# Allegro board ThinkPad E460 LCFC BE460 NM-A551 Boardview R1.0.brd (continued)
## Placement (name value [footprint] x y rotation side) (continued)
RC55  49.9_0402_1%  [R_0402]  119.18 129.19 270 top
RC56  49.9_0402_1%  [R_0402]  102.57 100.9 270 top
RC67  10K_0402_5%  [R_0402]  111.73 146.58 0 top
RC70  10K_0402_5%  [R_0402]  109.84 145.9 270 top
RC71  10K_0402_5%  [R_0402]  113.15 145.39 270 top
RC74  10K_0402_5%  [R_0402]  110.46 142.72 90 top
RC83  1K_0402_5%  [R_0402]  105.14 143.62 270 top
RC84  20K_0402_5%  [R_0402]  106.03 143.62 270 top
RC88  10K_0402_5%  [R_0402]  90.66 138.08 0 top
RC92  499_0402_1%  [R_0402]  107.74 144.5 90 top
RC93  499_0402_1%  [R_0402]  108.63 144.5 90 top
RC95  8.2K_0402_5%  [R_0402]  123.55 150.83 90 top
RC97  1K_0402_5%  [R_0402]  123.63 154.46 180 top
RC98  20K_0402_5%  [R_0402]  121.09 154.46 180 top
RC99  1K_0402_5%  [R_0402]  123.63 153.58 180 top
RC100  20K_0402_5%  [R_0402]  121.09 153.58 180 top
RC101  1K_0402_5%  [R_0402]  123.63 152.69 180 top
RC102  33_0402_5%  [R_0402]  142.6 117.71 270 top
RC103  33_0402_5%  [R_0402]  135.11 117.71 270 top
RC104  1K_0402_5%  [R_0402]  86.14 93.5 0 bottom
RC105  1K_0402_5%  [R_0402]  86.85 94.83 90 bottom
RC106  4.7K_0402_5%  [R_0402]  111.56 149.13 180 top
RC107  4.7K_0402_5%  [R_0402]  108.74 149.64 0 top
RC108  10K_0402_5%  [R_0402]  88.77 137.41 270 bottom
RC109  0_0402_5%  [R0402_SHORT]  119.62 130.92 270 top
RC110  0_0402_5%  [R_0402]  141.59 137.9 270 top
RC117  1K_0402_5%  [R_0402]  143.11 136 270 top
RC118  1K_0402_5%  [R_0402]  141.59 136 270 top
RC120  100_0402_1%  [R_0402]  83.98 116.21 180 top
RC121  0_0402_5%  [R0402_SHORT]  83.98 117.1 180 top
RC123  10K_0402_5%  [R_0402]  88.04 99.73 0 top
RC124  0_0402_5%  [R0402_SHORT]  103.16 91.35 0 top
RC125  100_0402_1%  [R_0402]  101.38 91.35 0 top
RC126  0_0402_5%  [R0402_SHORT]  99.63 125.64 180 top
RC127  0_0402_5%  [R_0402]  91.42 141.76 270 top
RC132  0_0402_5%  [R0402_SHORT]  90.53 141.76 270 top
RC142  0_0402_5%  [R0402_SHORT]  83.98 117.99 180 top
RC143  100_0402_1%  [R_0402]  83.06 118.88 0 top
RC144  1K_0402_1%  [R_0402]  86.14 92.62 0 bottom
RC151  49.9_0402_1%  [R_0402]  116.11 129.18 270 top
RC152  49.9_0402_1%  [R_0402]  100.57 102.83 90 top
RC159  100K_0402_5%  [R_0402]  104.5 131.66 90 top
RC165  10K_0402_5%  [R_0402]  127.87 150.96 90 top
RC166  10K_0402_5%  [R_0402]  127.87 154.16 270 top
RC173  0_0603_5%  [R0603_SHORT]  134.36 146.5 180 top
RC176  0_0805_5%  [R0805_SHORT]  89.64 146.81 270 top
RC183  0_0402_5%  [R0402_SHORT]  103.16 89.82 0 top
RC184  100_0402_1%  [R_0402]  102.29 89.82 180 top
RC185  0_0402_5%  [R0402_SHORT]  99.63 126.52 180 top
RC189  100_0402_1%  [R_0402]  131.72 147.32 180 top
RC192  100_0402_1%  [R_0402]  130.8 148.28 0 top
RC200  49.9_0402_1%  [R_0402]  101.68 98.25 0 top
RC201  1K_0402_1%  [R_0402]  87.66 96.68 0 bottom
RC209  100K_0402_5%  [R_0402]  106.36 131.17 90 top
RC277  2.2K_0402_5%  [R_0402]  102.47 143.62 270 top
RC286  0_0402_5%  [R_0402]  131.73 154.46 0 top
RC287  2.2K_0402_5%  [R_0402]  103.36 143.62 270 top
RC292  10K_0402_5%  [R_0402]  175.29 108.59 0 top
RC294  1K_0402_5%  [R_0402]  88.03 98.8 0 top
RC295  0_0402_5%  [R0402_SHORT]  125.84 90.89 90 top
RC296  0_0402_5%  [R0402_SHORT]  116.62 151.8 0 bottom
RC297  1K_0402_5%  [R_0402]  134.09 114.79 270 top
RC298  8.2K_0402_5%  [R_0402]  130.84 140.49 0 top
RC299  1K_0402_5%  [R_0402]  137.27 115.42 270 top
RC300  20K_0402_5%  [R_0402]  123.55 149.97 270 top
RC301  20K_0402_5%  [R_0402]  134.98 114.79 270 top
RC302  20K_0402_5%  [R_0402]  136.38 115.42 270 top
RC304  0_0805_5%  [R_0805]  84.32 134.29 90 top
RC306  1K_0402_5%  [R_0402]  104.25 142.7 90 top
RC307  20K_0402_5%  [R_0402]  106.92 142.7 90 top
RC308  8.2K_0402_5%  [R_0402]  130.84 141.76 0 top
RC310  0_0402_5%  [R0402_SHORT]  143.11 137.9 270 top
RC311  0_0402_5%  [R0402_SHORT]  133.33 116.8 90 top
RC312  0_0402_5%  [R0402_SHORT]  134.8 128.43 180 top
RC313  0_0402_5%  [R0402_SHORT]  134.22 116.8 90 top
RC314  0_0402_5%  [R0402_SHORT]  132.11 128.43 0 top
RC315  0_0402_5%  [R0402_SHORT]  164.32 153.58 270 top
RC316  0_0402_5%  [R0402_SHORT]  165.4 153.59 0 top
RC317  0_0402_5%  [R0402_SHORT]  151.2 148.51 180 top
RC326  0_0402_5%  [R0402_SHORT]  88.75 129.06 180 bottom
RC330  0_0402_5%  [R0402_SHORT]  136.54 143.73 180 top
RC333  0_0402_5%  [R0402_SHORT]  136.39 142.87 270 top
RC341  0_0805_5%  [R0805_SHORT]  85.83 146.55 270 top
RC344  24.9_0402_1%  [R_0402]  100.44 108.69 270 top
RC347  10K_0402_5%  [R_0402]  176.21 107.71 180 top
RC348  33_0402_5%  [R_0402]  74.91 118.73 270 top
RC350  10K_0402_5%  [R_0402]  176.21 106.82 180 top
RC351  10K_0402_5%  [R_0402]  131.76 152.56 180 top
RC352  0_0402_5%  [R0402_SHORT]  139.24 141.91 0 top
RC353  10K_0402_5%  [R_0402]  132.7 152.61 90 top
RC354  1.5K_0402_5%  [R_0402]  87.57 132.13 180 bottom
RC355  100_0402_1%  [R_0402]  90.46 98.08 0 bottom
RC356  100_0402_1%  [R_0402]  90.46 99.85 0 bottom
RC358  100K_0402_1%  [R_0402]  90.52 101.34 0 top
RC359  113_0402_1%  [R_0402]  109.14 135.35 180 top
RC360  100_0402_1%  [R_0402]  101.63 134.65 0 top
RC361  200_0402_1%  [R_0402]  115.51 135.38 270 top
RC362  2.7K_0402_1%  [R_0402]  85.53 112.43 180 top
RC363  200_0402_1%  [R_0402]  111.03 134.12 270 top
RC364  0_0402_5%  [R0402_SHORT]  132.2 116.25 90 top
RC365  0_0402_5%  [R0402_SHORT]  130.93 139.49 180 top
RC366  0_0402_5%  [R_0402]  113.99 149.02 180 top
RC367  1K_0402_5%  [R_0402]  131.06 91.56 270 top
RC368  10K_0402_5%  [R_0402]  96.89 152.27 270 bottom
RC369  100_0402_1%  [R_0402]  83.08 119.78 0 top
RC370  100_0402_1%  [R_0402]  82.06 120.67 0 top
RC371  10K_0402_5%  [R_0402]  125.47 153.34 0 top
RC372  51_0402_1%  [R_0402]  89.43 107.74 180 bottom
RC373  51_0402_1%  [R_0402]  85.62 109.77 180 top
RC374  51_0402_1%  [R_0402]  85.62 108.45 180 top
RC375  10K_0402_5%  [R_0402]  105.48 145.87 270 top
RC376  10K_0402_5%  [R_0402]  104.59 145.87 270 top
RC377  2.2K_0402_1%  [R_0402]  103.7 145.87 270 top
RC378  2.2K_0402_1%  [R_0402]  102.81 145.87 270 top
RC379  10K_0402_5%  [R_0402]  201.39 125.65 180 top
RC380  1K_0402_5%  [R_0402]  137.43 135.53 180 top
RC382  10K_0402_5%  [R_0402]  84.68 95.83 90 top
RC383  1K_0402_5%  [R_0402]  86.53 101.16 270 top
RC384  0_0402_5%  [R_0402]  125.65 164.66 270 bottom
RC385  1K_0402_5%  [R_0402]  115.23 133.62 180 top
RC386  1K_0402_5%  [R_0402]  112.41 142.72 90 top
RC387  60.4_0402_1%  [R_0402]  90.49 99.44 0 top
RC388  10K_0402_5%  [R_0402]  100.81 144.62 90 top
RC389  0_0402_5%  [R0402_SHORT]  111.8 144.6 90 top
RC403  10K_0402_5%  [R_0402]  139.39 117.75 180 top
RC404  51_0402_1%  [R_0402]  89.48 103.32 180 bottom
RC405  0_0402_5%  [R_0402]  107.79 143.63 270 top
RC406  0_0402_5%  [R_0402]  111.45 142.72 90 top
RC407  0_0402_5%  [R_0402]  109.57 142.72 90 top
RC408  10K_0402_5%  [R_0402]  125.39 162.12 180 bottom
RC409  10K_0402_5%  [R_0402]  101.64 146.91 0 top
RC410  10K_0402_5%  [R_0402]  100.81 146.35 90 top
RD1  1.8K_0402_1%  [R_0402]  159.8 88.93 0 top
RD2  2_0402_1%  [R_0402]  159.8 88.04 0 top
RD3  1.8K_0402_1%  [R_0402]  163.43 89.01 270 top
RD4  24.9_0402_1%  [R_0402]  157.97 89.01 270 top
RD9  1.8K_0402_1%  [R_0402]  171.3 130.21 0 top
RD10  2_0402_1%  [R_0402]  159.32 130.5 90 top
RD11  1.8K_0402_1%  [R_0402]  172.19 127.54 0 top
RD12  24.9_0402_1%  [R_0402]  157.54 130.5 90 top
RD15  1.8K_0402_1%  [R_0402]  147.68 88.09 90 top
RD16  1.8K_0402_1%  [R_0402]  150.35 89.01 270 top
RD17  2_0402_1%  [R_0402]  146.79 88.09 90 top
RD18  24.9_0402_1%  [R_0402]  145.02 89.01 270 top
RD19  10K_0402_5%  [R_0402]  151.2 149.4 180 top
RD21  470_0402_5%  [R_0402]  158.27 100.49 0 top
RD23  100K_0402_5%  [R_0402]  175.46 133.9 180 top
RD24  10K_0402_5%  [R_0402]  174.54 133.02 0 top
RE1  43_0402_5%  [R_0402]  182.61 134.6 270 top
RE2  10K_0402_5%  [R_0402]  178.04 112.12 270 top
RE3  100K_0402_1%  [R_0402]  196.49 118 0 top
RE4  100K_0402_5%  [R_0402]  174.28 123.73 0 top
RE5  4.7K_0402_5%  [R_0402]  196.5 126.88 0 top
RE6  4.7K_0402_5%  [R_0402]  196.5 127.9 0 top
RE7  18K_0402_1%  [R_0402]  197.42 117.13 180 top
RE8  10K_0402_5%  [R_0402]  175.25 115.08 180 top
RE9  10K_0402_5%  [R_0402]  196 114.52 0 top
RE15  100K_0402_5%  [R_0402]  174.28 122.71 0 top
RE31  10K_0402_5%  [R_0402]  195.43 133.69 90 top
RE32  10K_0402_5%  [R_0402]  194.55 133.69 90 top
RE33  10K_0402_5%  [R_0402]  189.47 133.69 90 top
RE34  0_0402_5%  [R0402_SHORT]  189.41 136.05 180 top
RE39  10K_0402_5%  [R_0402]  196.5 125.13 0 top
RE40  0_0402_5%  [R0402_SHORT]  174.31 117.85 0 top
RE41  10K_0402_5%  [R_0402]  174.31 116.96 0 top
RE47  10K_0402_5%  [R_0402]  182.21 140.41 0 top
RE48  10K_0402_5%  [R_0402]  178.12 146.32 270 top
RE49  5.1K_0402_1%  [R_0402]  200.3 127.17 90 top
RE50  0_0402_5%  [R_0402]  203.12 110.03 180 bottom
RE51  0_0402_5%  [R_0402]  203.12 111.81 180 bottom
RE52  0_0402_5%  [R_0402]  203.12 110.92 180 bottom
RG1  0_0402_5%  [R_0402]  170.8 110.98 270 top
RG2  0_0402_5%  [R_0402]  175.3 104.95 0 top
RG4  100K_0402_5%  [R_0402]  175.24 114.21 180 top
RL1  0_0603_5%  [R0603_SHORT]  247.31 98.71 0 top
RL4  4.7K_0402_5%  [R_0402]  251.31 89.57 90 bottom
RL5  10K_0402_5%  [R_0402]  252.71 98.41 270 top
RL6  10K_0402_5%  [R_0402]  250.68 98.41 270 top
RL7  1K_0402_5%  [R_0402]  254.49 97.49 90 top
RL8  3.01K_0402_1%  [R_0402]  257.33 88.42 0 top
RL9  10K_0402_5%  [R_0402]  252.91 87.92 180 bottom
RL10  75_0805_5%  [R_0805]  266.94 80.33 90 bottom
RL11  75_0805_5%  [R_0805]  268.71 80.33 90 bottom
RL12  75_0805_5%  [R_0805]  274.19 79.97 90 bottom
RL13  75_0805_5%  [R_0805]  276.22 79.97 90 bottom
RL15  510_0402_1%  [R_0402]  284.39 86.01 0 top
RL16  510_0402_1%  [R_0402]  284.39 84.87 0 top
RL18  0_0402_5%  [R0402_SHORT]  250.17 87.92 0 bottom
RL22  47K_0402_5%  [R_0402]  245.4 100.11 0 bottom
RL23  100K_0402_5%  [R_0402]  241.03 100.79 90 bottom
RL24  10K_0402_5%  [R_0402]  246.31 99.09 180 bottom
RL25  0_0402_5%  [R_0402]  239.63 101.71 270 bottom
RL26  0_0402_5%  [R_0402]  253.21 88.03 180 top
RM2  0_0402_5%  [R0402_SHORT]  265.03 151.11 90 top
RM5  0_0402_5%  [R0402_SHORT]  263.63 151.11 90 top
RM8  0_0402_5%  [R0402_SHORT]  261.73 151.11 90 top
RM11  0_0402_5%  [R0402_SHORT]  260.33 151.11 90 top
RM13  0_0402_5%  [R0402_SHORT]  267.66 145.31 0 top
RM14  0_0603_5%  [R_0603]  254.31 139.24 0 top
RM15  0_0402_5%  [R0402_SHORT]  267.65 143.97 0 top
RM16  0_0402_5%  [R_0402]  266.73 141.4 0 top
RM17  0_0402_5%  [R_0402]  266.73 142.91 0 top
RM18  1M_0402_5%  [R_0402]  255.33 140.49 180 top
RM19  4.99K_0402_1%  [R_0402]  254.42 142.41 0 top
RM20  10K_0402_1%  [R_0402]  269.93 146.23 180 top
RM21  4.7K_0402_5%  [R_0402]  254.24 147.81 270 top
RM22  4.7K_0402_5%  [R_0402]  254.42 144.19 0 top
RM23  4.7K_0402_5%  [R_0402]  262.74 154.01 270 top
RM24  4.7K_0402_5%  [R_0402]  255.12 146.9 90 top
RM25  4.7K_0402_5%  [R_0402]  255.34 143.3 180 top
RM26  4.7K_0402_5%  [R_0402]  262.74 150.2 90 top
RM27  4.7K_0402_5%  [R_0402]  269.02 148.01 270 top
RM28  4.7K_0402_5%  [R_0402]  269.91 147.1 90 top
RM29  0_0402_5%  [R_0402]  254.42 145.97 0 top
RM30  0_0402_5%  [R_0402]  254.42 145.08 0 top
RM31  10K_0402_1%  [R_0402]  266.74 147.37 0 top
RM32  4.7K_0402_5%  [R_0402]  258.31 151.13 270 top
RM33  4.7K_0402_5%  [R_0402]  259.2 150.21 90 top
RM34  4.99K_0402_1%  [R_0402]  254.42 141.52 0 top
RPC2  33_0804_8P4R_5%  [RP_0804_8P4R]  131.44 113.63 90 top
RPC6  10K_0804_8P4R_5%  [RP_0804_8P4R]  134.79 149.63 0 top
RPC8  10K_0804_8P4R_5%  [RP_0804_8P4R]  112.24 151.35 90 bottom
RPC10  10K_0804_8P4R_5%  [RP_0804_8P4R]  110.91 155.34 0 top
RPC15  10K_0804_8P4R_5%  [RP_0804_8P4R]  89.01 130.21 0 bottom
RPC18  10K_0804_8P4R_5%  [RP_0804_8P4R]  131.87 149.9 180 top
RPC22  10K_0804_8P4R_5%  [RP_0804_8P4R]  126.97 148.94 270 top
RPC23  33_0804_8P4R_5%  [RP_0804_8P4R]  137.92 132.43 90 top
RPC24  33_0804_8P4R_5%  [RP_0804_8P4R]  141.6 132.43 90 top
RPC26  10K_0804_8P4R_5%  [RP_0804_8P4R]  90.15 134.53 180 bottom
RPC200  10K_0804_8P4R_5%  [RP_0804_8P4R]  126.41 150.54 180 top
RPE1  10K_0804_8P4R_5%  [RP_0804_8P4R]  174.16 121.43 0 top
RPE2  10K_0804_8P4R_5%  [RP_0804_8P4R]  182.24 111.09 90 top
RPE3  10K_0804_8P4R_5%  [RP_0804_8P4R]  179.32 111.09 90 top
RPE4  100K_0804_8P4R_5%  [RP_0804_8P4R]  193.39 134.85 270 top
RPE5  2.2K_0804_8P4R_5%  [RP_0804_8P4R]  184.75 137.77 270 top
RRE20  4.99K_0402_1%  [R_0402]  249.37 82.66 270 top
RRE21  4.7K_0402_5%  [R_0402]  244.58 81.74 90 top
RRE22  4.7K_0402_5%  [R_0402]  245.52 81.55 0 top
RRE23  4.7K_0402_5%  [R_0402]  247.38 81.74 90 top
RRE24  4.7K_0402_5%  [R_0402]  244.71 93.07 270 top
RRE25  4.7K_0402_5%  [R_0402]  250.22 86.01 0 bottom
RRE26  4.7K_0402_5%  [R_0402]  242.81 82.66 270 top
RRE27  4.7K_0402_5%  [R_0402]  243.69 82.66 270 top
RRE28  4.7K_0402_5%  [R_0402]  246.44 82.44 180 top
RRE29  4.7K_0402_5%  [R_0402]  248.27 82.66 270 top
RRE30  4.7K_0402_5%  [R_0402]  245.73 92.16 90 top
RRE32  0_0402_5%  [R0402_SHORT]  249.28 91.14 90 bottom
RV1  0_0402_5%  [R_0402]  74.24 155.49 180 top
RV2  0_0402_5%  [R_0402]  75.1 153.46 0 top
RV3  0_0402_5%  [R_0402]  74.24 154.61 180 top
RV4  0_0402_5%  [R_0402]  74.24 153.72 180 top
RV5  40.2_0402_1%  [R_0402]  51.16 133.69 90 bottom
RV6  100_0402_5%  [R_0402]  49.13 134.6 270 bottom
RV7  40.2_0402_1%  [R_0402]  46.08 133.69 90 bottom
RV8  100_0402_5%  [R_0402]  47.1 134.6 270 bottom
RV9  49.9_0402_1%  [R_0402]  64.6 170.11 270 top
RV10  10_0402_5%  [R_0402]  64.25 168.33 270 top
RV11  5.1K_0402_5%  [R_0402]  63.36 167.41 90 top
RV12  51.1_0402_1%  [R_0402]  50.12 173.18 270 top
RV13  51.1_0402_1%  [R_0402]  43.14 172.35 90 top
RV14  120_0402_1%  [R_0402]  52.18 133.69 90 bottom
RV15  10K_0402_5%  [R_0402]  14.71 130.54 270 top
RV16  243_0402_1%  [R_0402]  22.56 144.23 90 bottom
RV17  243_0402_1%  [R_0402]  20.17 130.54 270 top
RV18  4.99K_0402_1%  [R_0402]  20.73 145.16 270 bottom
RV19  4.99K_0402_1%  [R_0402]  19.84 144.24 90 bottom
RV24  4.99K_0402_1%  [R_0402]  21.01 145.16 270 top
RV25  4.99K_0402_1%  [R_0402]  21.9 144.24 90 top
RV26  40.2_0402_1%  [R_0402]  22.91 130.55 270 top
RV27  40.2_0402_1%  [R_0402]  22.02 129.64 90 top
RV28  243_0402_1%  [R_0402]  23.32 150.85 270 top
RV29  243_0402_1%  [R_0402]  18.47 164.18 90 bottom
RV30  4.99K_0402_1%  [R_0402]  19.79 149.97 90 top
RV31  4.99K_0402_1%  [R_0402]  20.68 150.88 270 top
RV36  4.99K_0402_1%  [R_0402]  22.48 149.96 90 bottom
RV37  4.99K_0402_1%  [R_0402]  21.13 150.87 270 bottom
RV38  40.2_0402_1%  [R_0402]  20.88 164.18 90 bottom
RV39  40.2_0402_1%  [R_0402]  19.99 165.1 270 bottom
RV40  1K_0402_5%  [R_0402]  47.12 169.45 0 bottom
RV43  10K_0402_5%  [R_0402]  67.03 134.93 270 bottom
RV44  100K_0402_5%  [R_0402]  64.52 131.88 270 bottom
RV47  1.69K_0402_1%  [R_0402]  53.98 134.58 270 bottom
RV48  1K_0402_1%  [R_0402]  53.09 134.58 270 bottom
RV49  10K_0402_5%  [R_0402]  83.74 138.27 0 top
RV50  10K_0402_5%  [R_0402]  85.17 139.28 180 top
RV51  0_0402_5%  [R_0402]  86.75 142.02 270 top
RV52  10K_0402_5%  [R_0402]  88.53 141.1 90 top
RV53  10K_0402_5%  [R_0402]  87.64 142.02 270 top
RV54  4.7K_0402_5%  [R_0402]  64.24 167.62 270 bottom
RV55  4.7K_0402_5%  [R_0402]  63.35 167.55 270 bottom
RV61  10K_0402_5%  [R_0402]  46.26 176 270 top
RV62  1K_0402_1%  [R_0402]  46.84 173.34 270 top
RV63  10K_0402_5%  [R_0402]  49.13 168 270 bottom
RV64  10K_0402_5%  [R_0402]  46.46 168 270 bottom
RV65  10K_0402_5%  [R_0402]  45.57 168 270 bottom
RV66  10K_0402_5%  [R_0402]  44.69 168 270 bottom
RV67  10K_0402_5%  [R_0402]  47.35 167.09 90 bottom
RV68  1M_0402_5%  [R_0402]  69.54 144.39 0 bottom
RV70  4.7K_0402_5%  [R_0402]  60.68 167.57 270 bottom
RV71  4.7K_0402_5%  [R_0402]  61.57 167.57 270 bottom
RV72  4.7K_0402_5%  [R_0402]  61.3 169.76 90 top
RV73  4.7K_0402_5%  [R_0402]  61.31 168.35 270 top
RV74  10K_0402_5%  [R_0402]  48.24 168 270 bottom
RV75  10K_0402_5%  [R_0402]  51.91 159.29 0 top
RV76  5.11K_0402_1%  [R_0402]  45.37 176 270 top
RV77  1K_0402_1%  [R_0402]  45.96 173.34 270 top
RV78  0_0402_5%  [R_0402]  70.03 160.69 180 bottom
RV79  0_0402_5%  [R_0402]  70.03 159.8 180 bottom
RV80  4.7K_0402_5%  [R_0402]  75.56 147.54 180 bottom
RV81  16.2K_0402_1%  [R_0402]  65.13 167.62 270 bottom
RV82  10K_0402_5%  [R_0402]  59.75 143.8 180 top
RV83  10K_0402_5%  [R_0402]  69.59 146.88 180 bottom
RV84  10K_0402_5%  [R_0402]  62.46 167.57 270 bottom
RV86  47K_0402_5%  [R_0402]  60.31 129.01 270 bottom
RV87  2.2K_0402_5%  [R_0402]  58.53 128.1 90 bottom
RV88  100K_0402_5%  [R_0402]  59.42 128.1 90 bottom
RV89  33_0402_5%  [R_0402]  19.06 168.06 0 bottom
RV90  33_0402_5%  [R_0402]  19.97 172.5 180 bottom
RV91  10K_0402_5%  [R_0402]  19.04 168.93 0 bottom
RV92  10K_0402_5%  [R_0402]  19.06 171.62 0 bottom
RV93  10K_0402_5%  [R_0402]  19.97 169.84 180 bottom
RV94  10K_0402_5%  [R_0402]  19.97 170.73 180 bottom
RV95  10K_0402_5%  [R_0402]  27.41 173.69 90 bottom
RV96  33_0402_5%  [R_0402]  26.18 169.74 0 bottom
RV97  33_0402_5%  [R_0402]  26.18 170.63 0 bottom
RV98  8.45K_0402_1%  [R_0402]  70.21 150.73 270 bottom
RV99  2K_0402_1%  [R_0402]  69.32 150.73 270 bottom
RV100  10K_0402_1%  [R_0402]  70.87 154.67 270 bottom
RV101  4.75K_0402_1%  [R_0402]  69.98 153.75 90 bottom
RV102  10K_0402_1%  [R_0402]  70.21 152 90 bottom
RV103  4.75K_0402_1%  [R_0402]  69.32 152.91 270 bottom
RV104  3.24K_0402_1%  [R_0402]  70.21 148.09 90 bottom
RV105  5.62K_0402_1%  [R_0402]  69.32 149 270 bottom
RV106  4.7K_0402_5%  [R_0402]  75.56 146.65 180 bottom
RV107  0_0402_5%  [R_0402]  69.12 155.61 0 bottom
RV108  0_0402_5%  [R_0402]  68.63 156.63 0 bottom
RV109  0_0402_5%  [R_0402]  68.61 157.77 0 bottom
RV111  2.2K_0402_5%  [R_0402]  71.55 162.82 0 bottom
RV112  0_0402_5%  [R_0402]  48.24 167.62 270 top
RV113  0_0402_5%  [R_0402]  48.11 175.09 90 top
RV114  0_0402_5%  [R0402_SHORT]  47.15 176 270 top
RV115  4.7K_0402_5%  [R_0402]  75.5 148.94 180 bottom
RV116  0_0402_5%  [R0402_SHORT]  26.25 170.39 180 top
RV117  0_0402_5%  [R0402_SHORT]  26.25 171.3 180 top
RV118  10K_0402_5%  [R_0402]  75.09 155.61 0 bottom
RV119  10K_0402_5%  [R_0402]  75.36 156.63 0 bottom
RV120  10K_0402_5%  [R_0402]  75.09 157.77 0 bottom
RV121  10K_0402_5%  [R_0402]  73.01 155.63 270 bottom
RV122  10K_0402_5%  [R_0402]  74 154.69 90 bottom
RV123  10K_0402_5%  [R_0402]  73.07 156.63 0 bottom
RV124  10K_0402_5%  [R_0402]  71.04 156.63 0 bottom
RV125  10K_0402_5%  [R_0402]  73.06 157.77 0 bottom
RV126  10K_0402_5%  [R_0402]  71.03 157.77 0 bottom
RV129  10K_0402_5%  [R_0402]  39.66 125.81 90 bottom
RV130  0_0402_5%  [R0402_SHORT]  45.5 132.24 0 bottom
RV134  47K_0402_5%  [R_0402]  73.64 158.35 270 top
RV135  10K_0402_5%  [R_0402]  72.75 157.44 90 top
RV136  0_0402_5%  [R0402_SHORT]  76.99 152.18 0 bottom
RV137  100K_0402_5%  [R_0402]  77.91 153.07 180 bottom
RV138  470_0402_5%  [R_0402]  78.92 157.39 180 bottom
RV139  10K_0402_5%  [R_0402]  76.99 150.4 0 bottom
RV140  0_0402_5%  [R_0402]  75.5 150.65 180 bottom
RV141  300_0402_5%  [R_0402]  51.29 129.55 180 bottom
RV142  10K_0402_5%  [R_0402]  55.89 131.48 180 bottom
RV143  100K_0402_5%  [R_0402]  38.77 125.81 90 bottom
RV152  100K_0402_5%  [R_0402]  55.05 174.33 180 top
RV153  22K_0402_5%  [R_0402]  55.91 174.33 0 top
SW1  NTC010-AK1G-B160T_4P  [SW_NTC010-AK1G-B160T_4P]  261 161.82 20 top
T3  PAD  [TPC12]  91.8 104.81 180 bottom
T4  PAD  [TPC12]  90.53 105.7 180 bottom
T5  PAD  [TPC12]  90.66 102.9 180 bottom
T6  PAD  [TPC12]  90.53 104.17 180 bottom
T8  PAD  [TPC12]  101.89 104.88 0 top
T9  PAD  [TPC12]  88.64 108.68 180 bottom
T10  PAD  [TPC12]  85.18 111.4 0 top
T11  PAD  [TPC12]  89.96 108.73 180 bottom
T12  PAD  [TPC12]  85.62 107.56 0 top
T13  PAD  [TPC12]  90.32 106.98 180 bottom
T14  PAD  [TPC12]  91.8 106.08 180 bottom
T15  PAD  [TPC12]  91.25 108.71 180 bottom
T16  PAD  [TPC12]  84.75 102.66 0 top
T18  PAD  [TPC12]  131.51 133.62 270 top
T19  PAD  [TPC12]  90.42 110.16 180 bottom
T20  PAD  [TPC12]  91.51 107.44 180 bottom
T23  PAD  [TPC12]  253.6 97.95 180 top
T24  PAD  [TPC12]  251.7 97.95 180 top
T49  PAD  [TPC12]  115.07 130.69 0 top
T50  PAD  [TPC12]  117.34 132.38 0 top
T52  PAD  [TPC12]  102.22 111.54 0 top
T53  PAD  [TPC12]  100.69 111.54 0 top
T56  PAD  [TPC12]  116.32 131.62 0 top
T59  PAD  [TPC12]  91.17 95.16 180 bottom
T60  PAD  [TPC12]  94.43 102.28 180 bottom
T61  PAD  [TPC12]  115.44 132.74 0 top
T62  PAD  [TPC12]  128.24 144.06 0 top
TC118  PAD  [TPC12]  118.08 130.32 0 top
TC119  Test_Point_40MIL  [TPC40]  111.7 141.09 180 bottom
TC120  Test_Point_40MIL  [TPC40]  111.93 139.7 180 bottom
TG1  PAD  [TPC12]  176.07 105.89 0 top
TL1  BOTHHAND-NA69LF  [TAIMA_IH-189-A_24P]  263.93 93.67 0 bottom
TP22  PAD  [TPC12]  91.28 136.83 0 top
TP23  PAD  [TPC12]  88.11 136.8 0 top
TP24  PAD  [TPC12]  115.16 151.79 180 bottom
TP25  PAD  [TPC12]  90.26 139.11 180 bottom
TP26  PAD  [TPC12]  113.78 151.84 180 bottom
TP27  PAD  [TPC12]  91.64 139.29 180 bottom
TP29  PAD  [TPC12]  128.8 139.09 0 top
TP30  PAD  [TPC12]  88.89 139.37 180 bottom
TP31  PAD  [TPC12]  88.87 140.81 180 bottom
TP32  PAD  [TPC12]  89.96 97.43 0 top
TP33  PAD  [TPC12]  91.79 140.74 180 bottom
TP34  PAD  [TPC12]  117.32 155.24 180 bottom
TP35  PAD  [TPC12]  115.94 155.27 180 bottom
TP36  PAD  [TPC12]  90.14 96.69 180 bottom
TP37  PAD  [TPC12]  128.28 90.43 0 top
TP38  PAD  [TPC12]  89.78 95.3 180 bottom
TP39  PAD  [TPC12]  128.25 91.75 0 top
TP40  PAD  [TPC12]  91.54 96.77 180 bottom
TP41  PAD  [TPC12]  88.24 95.31 180 bottom
TP42  PAD  [TPC12]  87.11 91.26 180 bottom
TP43  PAD  [TPC12]  113.96 131.44 0 top
TP44  PAD  [TPC12]  88.99 92.43 0 top
TP45  PAD  [TPC12]  114.09 132.66 0 top
TP46  PAD  [TPC12]  90.29 92.45 0 top
TP47  PAD  [TPC12]  91.61 93.8 0 top
TP48  PAD  [TPC12]  88.9 92.63 180 bottom
TP49  PAD  [TPC12]  114.52 153.46 180 bottom
TP50  PAD  [TPC12]  88.86 89.92 180 bottom
TP51  PAD  [TPC12]  115.92 153.46 180 bottom
TP52  PAD  [TPC12]  90.41 92.7 180 bottom
TP53  PAD  [TPC12]  88.82 91.28 180 bottom
TP54  PAD  [TPC12]  117.34 156.64 180 bottom
TP55  PAD  [TPC12]  88.76 88.56 180 bottom
TP56  PAD  [TPC12]  90.3 89.86 180 bottom
TP57  PAD  [TPC12]  90.32 88.49 180 bottom
TP58  PAD  [TPC12]  90.3 91.23 180 bottom
TP59  PAD  [TPC12]  119.4 135.07 0 top
TP60  PAD  [TPC12]  117.06 134.92 0 top
TP61  PAD  [TPC12]  90.26 95.07 0 top
TP62  PAD  [TPC12]  90.29 93.77 0 top
TP63  PAD  [TPC12]  91.59 95.09 0 top
TP64  PAD  [TPC12]  90.04 137.71 180 bottom
TP65  PAD  [TPC12]  88.99 93.7 0 top
TP66  PAD  [TPC12]  91.79 137.46 180 bottom
TP67  PAD  [TPC12]  91.41 136.04 180 bottom
TP68  PAD  [TPC12]  90.01 136.29 180 bottom
TP69  Test_Point_40MIL  [TPC40]  267.41 140.01 0 top
TP70  Test_Point_40MIL  [TPC40]  252.6 141.02 90 top
TP71  Test_Point_40MIL  [TPC40]  244.96 91.22 180 bottom
TP72  Test_Point_40MIL  [TPC40]  209.1 91.17 0 top
TP73  Test_Point_40MIL  [TPC40]  224.97 91.35 90 top
TP74  PAD  [TPC12]  90.26 140.76 180 bottom
TP85  PAD  [TPC12]  100.93 110.13 0 top
TP86  PAD  [TPC12]  103.24 109.74 0 top
TP87  PAD  [TPC12]  114.14 122.47 0 top
TP88  PAD  [TPC12]  114.06 124.76 0 top
TP89  PAD  [TPC12]  91.18 93.84 180 bottom
TP90  PAD  [TPC12]  91.05 91.28 0 top
TP91  PAD  [TPC12]  91.71 110.18 180 bottom
TP92  PAD  [TPC12]  127.07 92.44 0 top
TP93  PAD  [TPC12]  127.08 91.13 0 top
TP94  PAD  [TPC12]  89.09 86.6 180 bottom
TP95  PAD  [TPC12]  90.46 86.51 180 bottom
TP96  PAD  [TPC12]  88.99 94.97 0 top
TP97  PAD  [TPC12]  91.36 97.33 0 top
TP98  PAD  [TPC12]  125.51 95.94 0 top
TP99  PAD  [TPC12]  126.8 95.94 0 top
TP100  PAD  [TPC12]  124.36 99.8 0 top
TP101  PAD  [TPC12]  128.09 95.88 0 top
TP102  PAD  [TPC12]  89.76 136.83 0 top
TP103  PAD  [TPC12]  107.99 131.34 0 top
TP104  PAD  [TPC12]  113.35 147.44 0 top
TP105  PAD  [TPC12]  100.63 128.82 0 top
TP106  PAD  [TPC12]  103.98 134.79 0 top
TP107  PAD  [TPC12]  90.26 142.13 180 bottom
TP108  PAD  [TPC12]  90.8 128.57 180 bottom
TP109  PAD  [TPC12]  88.36 126.79 180 bottom
TP110  PAD  [TPC12]  89.5 127.68 180 bottom
TP111  PAD  [TPC12]  99.56 129.99 0 top
TP112  PAD  [TPC12]  87.37 125.78 180 bottom
TP113  PAD  [TPC12]  100.65 106.19 0 top
TP115  Test_Point_40MIL  [TPC40]  84.83 104.08 0 top
TP116  Test_Point_40MIL  [TPC40]  91.84 103.5 180 bottom
TP117  Test_Point_40MIL  [TPC40]  88.12 139.61 90 top
TP120  Test_Point_40MIL  [TPC40]  129.15 163.75 0 top
TP121  Test_Point_40MIL  [TPC40]  124.57 158.66 0 top
TP124  Test_Point_40MIL  [TPC40]  121.91 156.94 0 top
TP125  Test_Point_40MIL  [TPC40]  129.58 144.76 0 top
TP126  Test_Point_40MIL  [TPC40]  179.44 136.32 0 top
TP127  Test_Point_40MIL  [TPC40]  137.03 155.65 0 top
TP128  Test_Point_40MIL  [TPC40]  201.85 122.27 0 top
TP129  Test_Point_40MIL  [TPC40]  195.32 125.65 0 top
TP927  PAD  [TPC12]  89.77 93.88 180 bottom
TP928  PAD  [TPC12]  88.32 93.83 180 bottom
TP929  PAD  [TPC12]  91.61 92.5 0 top
TP930  PAD  [TPC12]  89.55 91.21 0 top
TP931  PAD  [TPC12]  84.68 106.42 0 top
TP932  PAD  [TPC12]  85.44 105.33 0 top
TP933  PAD  [TPC12]  114.55 155.24 180 bottom
TP934  PAD  [TPC12]  117.29 153.49 180 bottom
TP935  PAD  [TPC12]  126.5 99.99 0 top
TP936  PAD  [TPC12]  125.57 93.15 0 top
TP937  PAD  [TPC12]  128.33 88.98 0 top
TP938  PAD  [TPC12]  122.92 99.84 0 top
TP940  Test_Point_40MIL  [TPC40]  124.77 160.05 180 top
TP941  Test_Point_40MIL  [TPC40]  270.12 115.62 0 top
TPV1  Test_Point_20MIL  [TPC20]  61.27 165.44 180 bottom
TPV2  Test_Point_20MIL  [TPC20]  62.47 164.98 180 bottom
TPV3  Test_Point_20MIL  [TPC20]  52.12 157.02 0 top
TPV4  Test_Point_20MIL  [TPC20]  51.15 166.44 180 bottom
TPV5  Test_Point_20MIL  [TPC20]  51.42 165.18 180 bottom
TPV6  Test_Point_20MIL  [TPC20]  53.19 158.27 0 top
TPV7  Test_Point_20MIL  [TPC20]  49.8 165.81 180 bottom
TPV8  Test_Point_20MIL  [TPC20]  45.31 166.07 180 bottom
TPV9  Test_Point_20MIL  [TPC20]  48.29 166.05 180 bottom
TPV10  Test_Point_20MIL  [TPC20]  46.74 166.07 180 bottom
TPV11  Test_Point_20MIL  [TPC20]  46.06 164.98 180 bottom
TPV12  Test_Point_20MIL  [TPC20]  70.75 161.68 180 bottom
TPV13  Test_Point_20MIL  [TPC20]  63.74 165.26 180 bottom
TPV14  Test_Point_32MIL  [TPC32]  75.17 153.45 180 bottom
TPV15  Test_Point_32MIL  [TPC32]  48.75 169.7 90 top
TPV16  Test_Point_32MIL  [TPC32]  44.05 174.78 0 top
TPV17  Test_Point_20MIL  [TPC20]  51.94 158.22 0 top
TPV18  Test_Point_20MIL  [TPC20]  50.78 156.62 0 top
TPV19  Test_Point_20MIL  [TPC20]  62.96 157.58 0 top
TPV20  Test_Point_20MIL  [TPC20]  58.27 154.36 0 top
TPV21  Test_Point_20MIL  [TPC20]  62.93 158.9 0 top
TPV22  Test_Point_20MIL  [TPC20]  62.29 156.47 0 top
TPV23  Test_Point_20MIL  [TPC20]  60.71 157.97 0 top
TPV24  Test_Point_20MIL  [TPC20]  61.87 159.61 0 top
TPV25  Test_Point_20MIL  [TPC20]  68.54 165.08 180 bottom
TPV26  Test_Point_20MIL  [TPC20]  67.55 166 180 bottom
TPV27  Test_Point_20MIL  [TPC20]  60.55 159.27 0 top
TPV28  Test_Point_20MIL  [TPC20]  59.24 159.29 0 top
TPV29  Test_Point_20MIL  [TPC20]  58.09 157.96 0 top
TPV30  Test_Point_20MIL  [TPC20]  65.01 165.26 180 bottom
TPV31  Test_Point_20MIL  [TPC20]  66.4 165.26 180 bottom
TPV32  Test_Point_20MIL  [TPC20]  56.64 159.34 0 top
TPV33  Test_Point_20MIL  [TPC20]  57.96 159.45 90 top
TPV34  Test_Point_20MIL  [TPC20]  68.82 158.78 180 bottom
U1  F75303M_MSOP10  [EMC1403-2-AIZL-TR_MSOP10]  41.41 126.15 270 top
U3  -  [G524B1T11U_SOT23-5]  70.42 115.59 225 bottom
U4  -  [G524B1T11U_SOT23-5]  63.92 118.89 135 bottom
U5  -  [PS8713BTQFN24GTR2A_TQFN24_4X4]  205.11 93.37 0 top
U6  -  [PS8713BTQFN24GTR2A_TQFN24_4X4]  222.51 93.27 0 top
U8  -  [AH9246-W-7_SC59-3]  295.51 44.74 90 top
U11  -  [TPS22966DPUR_WSON14_2X3]  219.62 136.69 180 top
U14  -  [TPS2546RTER_QFN16_4X4]  137.71 69.5 180 top
U15  -  [G524B2T11U_SOT23-5]  280.97 24.52 0 bottom
U16  -  [PS8713BTQFN24GTR2A_TQFN24_4X4]  265.06 119.98 0 top
U17  -  [G524B1T11U_SOT23-5]  180.27 153.9 0 top
U148  SIP32451DB-T2-GE1_WCSP4  [SIP32451DB-T2-GE1_WCSP_4P]  76.3 122.22 0 top
U149  -  [SLG5NT1533VTR_STDFN8-6_1X1P6]  76.47 115.86 90 top
UA1  -  [CX11852-11Z_QFN40_5X5]  189.48 55.26 180 top
UC1  SKYLAKE-U_BGA1356  [SKYLAKE-U_BGA_1356P-T]  98.79 137.07 90 bottom
UC3  -  [TC7SG17FE_SON5]  74.64 121.17 180 top
UC4M1  -  [W25Q32FVSSIQ_SO8]  140.57 119.5 0 top
UC8M1  -  [W25Q64FVSSIQ_SO8]  130.41 119.5 0 top
UE1  -  [IT8586E-AX_LQFP128_14X14]  177.83 129.17 270 top
UGSEN1  LIS3DHTR_LGA16_3x3  [LIS3DHTR_LGA16_3X3]  181.36 105.85 180 top
UL1  -  [WGI219LM-QREF-A0_QFN48_6X6]  252.04 89.84 0 top
UM1  -  [PI3EQXDP1201ZBEX_TQFN48_7X7]  257.67 147.31 0 top
UNK46J BARCODE  -  []  6.22 152.07 270 bottom
URE1  PS8407ATQFN40GTR2A4_TQFN40_5X5  [PS8401ATQFN40GTR2A4_TQFN40_5X5]  243.63 88.83 90 top
USROM1  -  [PCA24S08AD_SO8]  206.36 114.81 180 bottom
UTPM1  -  [NPCT650LA0YX_QFN32_5X5]  126.28 161.54 0 top
UV3  216-0858020-A0_FCBGA631  [216-0858020-A0_FCBGA_631P]  44.14 161.8 270 bottom
UV4  -  [MC74VHC1G08DFT2G_SC70-5]  67.04 130.09 180 bottom
UV5  K4W4G1646D-BC1A_FBGA96  [MT41K256M16HA107_FBGA_96P-A39P]  28.11 134.36 90 bottom
UV6  K4W4G1646D-BC1A_FBGA96  [MT41K256M16HA107_FBGA_96P-A39P]  28.11 140.76 270 top
UV7  K4W4G1646D-BC1A_FBGA96  [MT41K256M16HA107_FBGA_96P-A39P]  28.11 160.7 270 top
UV8  K4W4G1646D-BC1A_FBGA96  [MT41K256M16HA107_FBGA_96P-A39P]  28.11 154.3 90 bottom
UV9  -  [74AVCH2T45GD_XSON8_3X2]  21.45 170.41 90 bottom
UV11  -  [TPS22965DSGR_WSON8_2X2]  62.15 175.15 180 bottom
UV12  -  [TPS22965DSGR_WSON8_2X2]  60.25 175.15 0 top
YC1  32.768KHZ_12.5PF_9H03200042  [Y_9H03200042_2P]  125.89 143.05 90 top
YC2  24MHZ_10PF_8Y24000011  [Y_8Y24000011_4P]  90.02 116.11 270 bottom
YL1  25MHZ_10PF_8Y25000010  [Y_8Y25000010_4P]  255.2 84.97 0 top
YV1  27MHZ_16PF_7V27000011  [Y_X3G027000FG1H-HX_4P]  73.42 145.89 270 bottom

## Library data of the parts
C1 C9 C11 C13-C18 C20 C22 C28 C34 C36 C37 C50 C52 C53 C68 C70 C74 C115 C116 C119 CA1-CA6 CA8 CA10 CA12 CA13 CA16 CA17 CA19 CA22-CA24 CC1 CC6 CC7 CC18-CC22 CC25 CC26 CC70 CD3 CD17 CD30 CD32 CD49 CD58-CD60 CE2 CE4-CE10 CE14 CL1 CL2 CL4 CL5 CL9 CL11 CL12 CM1 CM2 CM5-CM12 CRE1 CRE3 CRE5 CRE7 CRE9 CRE11 CRE13 CRE14 CRE17-CRE20 CRE23 CV2 CV17-CV20 CV24 CV25 CV27 CV33-CV35 CV50 CV64 CV65 CV71 CV76 CV77 CV79 CV84-CV89 CV92 CV93 CV95-CV100 CV103 CV105-CV108 CV111-CV115 CV122-CV127 CV130 CV132-CV142 CV148-CV156 CV162 = CAP NP: signal model: CAP_NP_C_0402_0.1U_0402_10V7-K_0.1U_0402_10V7-K
C2-C5 C8 C10 C12 C19 C21 C23 C29-C33 C35 C40 C41 C51 C67 C69 C71-C73 C75 C85 C86 C118 C120-C122 C124-C127 C129-C132 C174-C189 C202-C207 C750 C751 C8496-C8499 C8535-C8538 C8542 CA7 CA9 CA11 CA14 CA15 CA18 CA25-CA32 CA42 CA43 CC2-CC5 CC9 CC23 CC24 CC68 CC69 CC86-CC94 CC101 CC102 CC243-CC257 CC283-CC294 CC329-CC344 CC500-CC512 CC514-CC519 CC522-CC529 CC537-CC540 CD1 CD2 CD8-CD16 CD18-CD21 CD23-CD26 CD29 CD31 CD33 CD38-CD48 CD51-CD57 CE1 CE3 CE11-CE13 CE16 CE17 CG1-CG3 CL3 CL7 CL8 CL10 CL13 CL17 CM3 CM4 CM13-CM20 CRE21 CRE22 CRE24 CRF1-CRF4 CV9 CV10 CV21 CV22 CV26 CV28-CV32 CV36-CV49 CV51-CV63 CV66 CV67 CV70 CV72-CV75 CV78 CV80-CV83 CV90 CV91 CV94 CV109 CV110 CV116-CV121 CV143-CV145 CV160 CV161 CV163-CV166 CV169 CV175-CV179 PC1 PC2 PC108 PC111 PC112 PC208 PC212 PC225 PC229-PC231 PC305 PC316 PC401 PC403 PC409 PC417 PC427 PC438 PC440 PC452 PC461 PC602 PC609 PC617 PC620 PC623 PC634 PC714 = CAP NP
C24-C27 CG4 CV1 CV104 CV131 = CAP NP: signal model: CAP_NP_C_0402_.01U_0402_16V7-K_.01U_0402_16V7-K
C38 = CAP NP: signal model: CAP_NP_C_0402_0.1U_0402_10V7_14_0.1U_0402_10V7-K-7
C39 = CAP NP: signal model: CAP_NP_C_0402_0.1U_0402_10V7_15_0.1U_0402_10V7-K-8
C44 C45 = CAP NP: room: TRACK
C123 C128 CD22 = CAP WP
C194 C197 C200 C201 CC535 CC536 = CAP NP_0
C747-C749 C8527 C8534 CA40 CC205-CC225 CC235-CC242 CC266-CC282 CC520 CC521 PC3-PC10 PC102-PC107 PC109 PC110 PC115-PC120 PC122-PC124 PC128 PC201 PC203 PC210 PC211 PC213 PC215 PC217 PC218 PC223 PC224 PC227 PC228 PC301 PC304 PC307-PC310 PC312 PC313 PC315 PC318 PC319 PC402 PC404-PC408 PC410-PC416 PC418-PC426 PC428-PC431 PC436 PC437 PC439 PC441 PC442 PC444 PC450 PC451 PC453 PC455 PC459 PC460 PC462 PC463 PC604 PC605 PC608 PC610 PC612 PC618 PC619 PC621 PC622 PC628 PC633 PC635-PC637 PC701-PC710 PC716 PC717 PC801-PC803 PC805-PC808 = P_CAP NP
CC46 CC47 CC49 CC50 CC52 CC58-CC61 CC95-CC97 CC99 CC530-CC532 = CAP NP_0: room: CPU
CL6 = CAP NP: room: LAN; signal model: CAP_NP_C_0402_0.1U_0402_10V7-K_0.1U_0402_10V7-K
CV3-CV8 = CAP NP: signal model: CAP_NP_C_0402_0.22U_0402_10V6-K_0.22U_0402_10V6-K
D1 PD7 = PESD5V0U2BT_SOT23-3
D2 D3 D7 D10 D11 D16-D18 DL1 DL2 = RCLAMP0524PATCT_SLP2510P8-10-9
D4 = AZC199-02SPR7G_SOT23-3
D5 = PJSOT24C_SOT23-3
D6 DA3-DA5 DV1 DV2 DV6 = RB751V-40_SOD323-2
D8 D9 D15 = IP4223CZ6_SO6-6
D22 D23 D25 D59-D64 DC23 = RB521CS-30GT2RA_VMN2-2
D24 = RB491D_SOT23-3
DA1 = BAT54CW_SOT323-3
DEV1 PD1-PD4 PD6 PD101-PD103 PD801 = P_RB751V-40_SOD323-2
DL3-DL6 = BS401N_1206-2
F1 = 1.1A_8V_SMD1812P110TF
F2 = 0.5A_8V_KMC3S050RY
FD1-FD6 = FM_2
H1-H8 H10-H21 H24-H28 = HOLE
IT1-IT8 TC119 TC120 TP69-TP73 TP115-TP117 TP120 TP121 TP124-TP129 TP940 TP941 = Test_Point_40MIL
J1 = JOPEN: User Part Number: PART#; room: EC
J5 J6 JC2 PJ201-PJ204 PJ301-PJ304 PJ701-PJ703 PJ801 PJ802 = P_JUMP_43X118
JBATT1 = P_FOX_GS73071-10272-M-7H
JC1 JV1 = P_JUMP
JCMOS1 JME1 = JOPEN: User Part Number: PART#; room: PCH
JCP = ACES_50506-01201-AT1
JCR = ACES_51530-01401-W01
JDIMM1 = LCN_DAN06-K4406-0102
JDIMM2 = LCN_DAN06-K4406-0103
JFAN = DRAPH_WS32050-S0471-HF
JFPB = ACES_88514-0060N-071
JHDD = HIGHS_SA2S0226-3201H
JHDMI = CONCR_099ATAC19NBLCNF
JKB = JAE_FL10F032HA2R3000
JLCD = I-PEX_20525-030E-02
JLINK = DRAPH_PJSS0296-MB21H
JLOGO JRTC = TE_2041180-2
JRJ451 = SINGA_2RJ3089-108211F
JSPK = TYCO_2041180-4
JTOUCH1 = ACES_50463-0104A-P01
JTP = JAE_FL10F012HA1R3000
JU3AC = HIGHS_FC5AF261-1151H
JUSB1 JUSB2 = SUYIN_020053GR009M283ZL
JV3 = JUMP
JWLBT = TE_2199230-8
L1-L4 L10-L14 = EXC24CH900U_4P: signal model: WCM-2012-900T_4P_KING_WCM-2012-_WCM-2012-900T_4P
L5 L6 L9 L15-L20 = EXC24CH900U_4P
LC1-LC5 R17 R58 R68 R70 R108 R269 R270 R272 R9447 R9449 R9492 RA1 RA4 RA30 RC40 RC109 RC126 RC132 RC173 RC176 RC183 RC185 RC295 RC296 RC310-RC317 RC326 RC330 RC333 RC341 RC352 RC364 RC365 RC389 RE40 RL1 RM2 RM5 RM8 RM11 RM13 RM15 RV114 RV130 RV136 = R-SHORT
LE1 LE2 LV4 LV5 = BLM18PG121SN1D_2P
LL1 = L: room: LAN
LV3 PL1-PL4 PL401 PL402 PL404 PL405 PL407 PL601 PL602 PL801 = L
PC101 PC314 = CAP NP: room: ESATA
PC113 PC114 PC121 PC125-PC127 PC202 PC209 PC214 PC216 PC226 PC302 PC303 PC317 PC432-PC435 PC445-PC449 PC456-PC458 PC464 PC601 PC603 PC606 PC607 PC611 PC615 PC616 PC624-PC627 PC631 PC632 PC718 PC804 = P_CAP NP: room: CPU_CORE
PC204-PC207 PC219-PC222 PC711-PC713 PC715 = CAP NP: room: CPU
PC306 = P_CAP NP: room: DDR_VTT
PC311 PC443 PC454 PC525-PC528 PC613 PC614 PC629 PC630 = P_CAP WP
PC465-PC524 = CAP NP: room: KB
PD5 = AZ5425-01F_DFN1006P2E2
PF1 = 7A_32V_0437007.WR
PF2 = P_12A_65V_451012MRL
PL101 PL102 PL201 PL202 PL301 PL403 PL406 PL408 PL603 PL604 PL701 = P_L
PQ1 = P_MMBT3906_SOT23-3_0
PQ2 = P_MMBT3904_SOT23-3_0
PQ3 PQ103 PQ105 Q4 Q26 QE1 QL3 QV4 QV7 QV11 = P_2N7002KW_SOT323-3
PQ4 PQ201 = P_2N7002BKS_SOT363-6
PQ101 PQ102 PQ104 = P_SIS406DN-T1-GE3_PAK1212-8-5
PQ106 PQ107 PQ301 PQ302 PQ407 PQ408 = P_AON7408L_DFN8-5_1
PQ401 PQ404 PQ601 PQ604 = P_TPCA8065-H_PPAK56-8-5_0
PQ402 PQ403 PQ405 PQ406 PQ602 PQ603 PQ605 PQ606 = P_TPCA8059-H_PPAK56-8-5_0
PR1-PR12 PR14 PR15 PR18 PR19 PR101 PR103-PR107 PR113-PR115 PR117 PR130-PR132 PR201 PR208 PR210 PR211 PR216 PR217 PR301 PR306 PR307 PR309 PR311 PR313 PR402 PR403 PR405 PR406 PR409-PR415 PR419 PR420 PR422 PR423 PR425 PR426 PR430-PR432 PR438-PR442 PR445-PR448 PR604 PR617 PR619 PR624 PR627-PR629 PR633 PR635 PR637 PR639 PR641-PR643 PR702 PR703 PR705 PR706 PR802 PR804 PR805 R722 RC95 RC98 RC298 RC300-RC302 RC307 RC308 RC359 RC360 = P_R
PR13 PR109 PR118 PR120-PR124 PR126 PR129 PR202 PR203 PR205 PR212 PR213 PR310 PR312 PR407 PR408 PR417 PR435 PR451 PR452 PR455 PR456 PR459 PR460 PR601-PR603 PR605 PR606 PR609-PR611 PR614 PR615 PR620 PR621 PR625 PR701 PR707 PR801 = P_R-SHORT
PR16 PR308 PR421 PR612 PR644 = P_R: room: VSB
PR17 PR206 PR207 PR209 PR215 PR302 PR305 PR401 PR404 PR416 PR418 PR424 PR427-PR429 PR433 PR434 PR436 PR437 PR443 PR444 PR613 PR622 PR623 PR626 PR634 PR638 PR640 R19 R20 R27-R29 R31-R36 R39-R42 R44 R46-R53 R55-R57 R61 R62 R66 R67 R69 R72 R74-R76 R83 R84 R88-R91 R93-R95 R98 R103-R107 R112-R117 R120 R150 R151 R156 R157 R159 R239-R261 R263-R268 R271 R273 R9446 R9448 R9450 R9451 R9455-R9468 R9494 RA2 RA3 RA13-RA15 RA17 RA18 RA20 RA21 RA23-RA25 RA29 RC1-RC6 RC8-RC10 RC12-RC14 RC16 RC19 RC20 RC24 RC26 RC27 RC29-RC32 RC34 RC47 RC48 RC52 RC54-RC56 RC67 RC70 RC71 RC74 RC83 RC88 RC97 RC99 RC102-RC105 RC110 RC120 RC123 RC125 RC127 RC143 RC151 RC159 RC165 RC166 RC184 RC189 RC192 RC200 RC201 RC209 RC277 RC286 RC287 RC292 RC294 RC297 RC299 RC304 RC306 RC344 RC347 RC348 RC350 RC351 RC353-RC356 RC361-RC363 RC366-RC380 RC382-RC388 RC403-RC410 RD1-RD4 RD9-RD12 RD15-RD19 RD21 RD23 RD24 RE1-RE9 RE15 RE32 RE33 RE41 RE47-RE52 RG1 RG2 RG4 RL4 RL5 RL7-RL9 RL15 RL16 RL22-RL26 RM18-RM34 RRE20-RRE30 RV1-RV7 RV11-RV13 RV15-RV19 RV24-RV31 RV36-RV40 RV47-RV54 RV61-RV68 RV70 RV71 RV77-RV84 RV86-RV88 RV91-RV95 RV98-RV109 RV111-RV113 RV120-RV126 RV129 RV134 RV135 RV137-RV143 RV152 RV153 = R
PR102 PR111 PR112 PR125 PR128 = P_R: room: CHARGER
PR108 PR110 = P_R: room: CPUCOREP
PR116 PR119 PR204 PR214 PR303 PR304 PR449 PR450 PR453 PR454 PR457 PR458 PR607 PR608 PR616 PR618 PR630-PR632 PR636 PR704 PR708 PR803 RC358 = P_R: room: CPU_CORE
PRT1-PRT6 = 540_0402NEW_30%_PRF15BB541NB6RC
PRT7 = P_100K_0402_1%_NCP15WF104F03RC
PRT401-PRT405 = P_MURAT_NCP03WF104F05RL
PRT601 = P_MURAT_NCP18XH103D03RB
PRT602 = P_470K_0402NEW_3%_TH05-4K474HR
PU1 = P_G718TM1U_SOT23-8
PU101 = P_BQ24780RUYR_QFN24_3
PU201 = P_SYX198BQNC_QFN10_3X3
PU202 = P_SYX198CQNC_QFN10_3X3
PU301 = P_RT8231AGQW_WQFN20_2
PU401 = P_NCP81208MNTXG_QFN48_6X6
PU402 PU404 = P_NCP81253MNTBG_DFN8_1
PU403 = P_NCP81151MNTBG_DFN8_0
PU601 = P_ISL62771HRTZ_TQFN40_5
PU701 = P_TPS51367RVER_QFN28_3P5X4P5
PU801 = P_RT8068AZQW_WDFN10_1
Q1 Q2 QV3 = MMST3904-7-F_SOT323-3
Q22 = AO3401A_SOT23-3
Q23 QV9 = AO4430L_SO8
Q24 Q28 QC1-QC3 QV2 QV8 QV10 = P_2N7002KDWH_SOT363-6
Q27 = AO3413_SOT23-3: room: CMOS
Q29 QG1 QL2 QV5 = AO3413_SOT23-3
QD1 = DTC115TMT2L_VMT3
QV13 = NTJD5121NT1G_SC88-6
R3-R5 R18 R21 R25 R26 R30 R37 R38 R43 R45 R54 R71 R118 R121 R122 RA16 RA19 RA22 RC53 RC92 RC93 RC108 RC117 RC118 RC144 RC152 RE31 RE39 RL6 RM14 RM16 RM17 RV8-RV10 RV14 RV43 RV44 RV55 RV74-RV76 RV115 RV118 RV119 = R: signal model: R_R_0402_0_0402_5%_0_0402_5%
R22 R24 R64 RA6 RA27 RA28 RC11 RC21 RC41 RC121 RC124 RC142 RE34 RL18 RRE32 RV116 RV117 = R-SHORT: signal model: R_R_0402_0_0402_5%_0_0402_5%
R59 R60 R63 R65 RC106 RC107 RV72 = R: room: TRACK
R111 = R: room: KB
RA5 RA7 RA11 RC101 RV89 RV90 RV96 RV97 = R: signal model: R_R_0402_33_0402_5%_33_0402_5%
RA8-RA10 RA12 = BLM18PG121SN1D_2P: signal model: R_R_0402_0_0402_5%_0_0402_5%
RC84 = P_R: signal model: R_R_0402_0_0402_5%_0_0402_5%
RC100 = P_R: signal model: R_R_0402_33_0402_5%_33_0402_5%
RL10-RL13 = R: room: LAN
RPC2 RPC6 RPC8 RPC10 RPC15 RPC18 RPC22-RPC24 RPC26 RPC200 RPE1-RPE5 = RP_8P4R
RV73 = R: room: TRACK; signal model: R_R_0402_0_0402_5%_0_0402_5%
SW1 = NTC010-AK1G-B160T_4P
T3-T6 T8-T16 T18-T20 T23 T24 T49 T50 T52 T53 T56 T59-T62 TC118 TG1 TP22-TP27 TP29-TP68 TP74 TP85-TP113 TP927-TP938 = PAD_6: room: CPU
TL1 = TAIMA_IH-189-A
TPV1-TPV13 TPV17-TPV34 = Test_Point_20MIL
TPV14-TPV16 = Test_Point_32MIL
U1 = EMC1403-2-AIZL-TR_MSOP10: room: THERMAL
U3 U4 U17 = G524B1T11U_SOT23-5
U5 U6 U16 = PS8713BTQFN24GTR2A_TQFN24_4X4
U8 = AH9246-W-7_SC59-3
U11 = TPS22966DPUR_WSON14_2X3
U14 = TPS2546RTER_QFN16_4X4
U15 = G524B2T11U_SOT23-5
U148 = P_SIP32451DB-T2-GE1_WCSP4
U149 = P_SLG5NT1533VTR_STDFN8-6_1X1P6
UA1 = CX11852-11Z_QFN40_5X5
UC1 = SKYLAKE-U_BGA1356
UC3 = TC7SG17FE_SON5
UC4M1 = W25Q32FVSSIQ_SO8
UC8M1 = W25Q64FVSSIQ_SO8
UE1 = IT8586E-AX_LQFP128_14X14
UGSEN1 = LIS3DHTR_LGA16_3X3
UL1 = WGI219LM-QREF-A0_QFN48_6X6
UM1 = PI3EQXDP1201ZBEX_TQFN48_7X7
URE1 = PS8401ATQFN40GTR2A4_TQFN40_5X5
USROM1 = PCA24S08AD_SO8
UTPM1 = NPCT650LA0YX_QFN32_5X5
UV3 = 216-0858020-A0_FCBGA631
UV4 = MC74VHC1G08DFT2G_SC70-5
UV5-UV8 = K4W4G1646B-HC11_FBGA96
UV9 = 74AVCH2T45GD_XSON8_3X2
UV11 UV12 = TPS22965DSGR_WSON8_2X2
YC1 = 32.768KHZ_12.5PF_9H03200042
YC2 = 24MHZ_10PF_8Y24000011
YL1 = 25MHZ_10PF_8Y25000010
YV1 = 27MHZ_16PF_X3G027000FG1H-HX

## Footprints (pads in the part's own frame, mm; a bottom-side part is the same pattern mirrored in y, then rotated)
2N7002BKS_SOT363-6
  oval 0.508x0.559 smd: 1(-0.75,-0.9) 3(0.75,-0.9) 4(0.75,0.9) 6(-0.75,0.9)
  oval 0.406x0.61 smd: 2(0,-0.9) 5(0,0.9)
2N7002KDWH_SOT363-6
  oval 0.356x0.889 smd: 1(0,0) 2(0.65,0) 3(1.3,0) 4(1.3,1.6) 5(0.65,1.6) 6(0,1.6)
2N7002KW_SOT323-3
  oval 0.813x0.914 smd: 1(0,0) 2(0.65,1.6) 3(-0.65,1.6)
74AVCH2T45GD_XSON8_3X2
  oval 0.305x1.143 smd: 1(0,0.2)
  oval 0.305x1.041 smd: 2(0.5,0.149) 3(1,0.149) 4(1.5,0.149) 5(1.5,2.749) 6(1,2.749) 7(0.5,2.749) 8(0,2.749)
216-0858020-A0_FCBGA_631P
  round 0.457 smd: A3(0.8,0) A30(20.8,0) A32(21.6,0) AK1(0,-20.8) AK3(0.8,-20.8) AK30(20.8,-20.8) AK32(21.6,-20.8) AM1(0,-21.6) AM3(0.8,-21.6) AM30(20.8,-21.6) AM32(21.6,-21.6) C1(0,-0.8) C3(0.8,-0.8) C30(20.8,-0.8) C32(21.6,-0.8)
  round 0.33 smd: A5(1.6,0) A28(20,0) AH1(0,-20) AH3(0.8,-20) AH5(1.6,-20) AH28(20,-20) AH30(20.8,-20) AH32(21.6,-20) AK5(1.6,-20.8) AK28(20,-20.8) AM5(1.6,-21.6) AM28(20,-21.6) C5(1.6,-0.8) C28(20,-0.8) E1(0,-1.6) E3(0.8,-1.6) E5(1.6,-1.6) E28(20,-1.6) E30(20.8,-1.6) E32(21.6,-1.6)
  round 0.406 smd: A7(3.2,0) A9(4.8,0) A11(6.4,0) A13(8,0) A15(9.6,0) A17(11.2,0) A19(12.8,0) A21(14.4,0) A23(16,0) A25(17.6,0) A27(19.2,0) AA1(0,-14.4) AA3(0.8,-14.4) AA5(1.6,-14.4) AA6(2.4,-14.4) AA27(19.2,-14.4) AA29(20.4,-14.4) AA31(21.2,-14.4) AB2(0.4,-15.2) AB4(1.2,-15.2) AB6(2.4,-15.2) AB7(3.2,-15) AB8(4,-15) AB9(4.8,-15) AB10(5.6,-15) AB23(16,-15) AB24(16.8,-15) AB25(17.6,-15) AB26(18.4,-15) AB27(19.2,-15.2) AB28(20,-15.2) AB30(20.8,-15.2) AB32(21.6,-15.2) AC1(0,-16) AC3(0.8,-16) AC5(1.6,-16) AC6(2.4,-16) AC7(3.2,-16) AC8(4,-16) AC9(4.8,-16) AC10(5.6,-16) AC11(6.6,-16) AC13(7.8,-16) AC14(9,-16) AC16(10.2,-16) AC17(11.4,-16) AC19(12.6,-16) AC20(13.8,-16) AC22(15,-16) AC23(16,-16) AC24(16.8,-16) AC25(17.6,-16) AC26(18.4,-16) AC27(19.2,-16) AC29(20.4,-16) AC31(21.2,-16) AD2(0.4,-16.8) AD4(1.2,-16.8) AD6(2.4,-16.8) AD7(3.2,-16.8) AD8(4,-16.8) AD9(4.8,-16.8) AD10(5.6,-16.8) AD11(6.6,-16.8) AD13(7.8,-16.8) AD14(9,-16.8) AD16(10.2,-16.8) AD17(11.4,-16.8) AD19(12.6,-16.8) AD20(13.8,-16.8) AD22(15,-16.8) AD23(16,-16.8) AD24(16.8,-16.8) AD25(17.6,-16.8) AD26(18.4,-16.8) AD27(19.2,-16.8) AD28(20,-16.8) AD30(20.8,-16.8) AD32(21.6,-16.8) AE1(0,-17.6) AE3(0.8,-17.6) AE5(1.6,-17.6) AE6(2.4,-17.6) AE7(3.2,-17.6) AE8(4,-17.6) AE9(4.8,-17.6) AE10(5.6,-17.6) AE11(6.6,-17.6) AE13(7.8,-17.6) AE14(9,-17.6) AE16(10.2,-17.6) AE17(11.4,-17.6) AE19(12.6,-17.6) AE20(13.8,-17.6) AE22(15,-17.6) AE23(16,-17.6) AE24(16.8,-17.6) AE25(17.6,-17.6) AE26(18.4,-17.6) AE27(19.2,-17.6) AE29(20.4,-17.6) AE31(21.2,-17.6) AF2(0.4,-18.4) AF4(1.2,-18.4) AF6(2.4,-18.4) AF7(3.2,-18.4) AF8(4,-18.4) AF9(4.8,-18.4) AF10(5.6,-18.4) AF11(6.6,-18.4) AF13(7.8,-18.4) AF14(9,-18.4) AF16(10.2,-18.4) AF17(11.4,-18.4) AF19(12.6,-18.4) AF20(13.8,-18.4) AF22(15,-18.4) AF23(16,-18.4) AF24(16.8,-18.4) AF25(17.6,-18.4) AF26(18.4,-18.4) AF27(19.2,-18.4) AF28(20,-18.4) AF30(20.8,-18.4) AF32(21.6,-18.4) AG1(0,-19.2) AG3(0.8,-19.2) AG5(1.6,-19.2) AG6(2.4,-19.2) AG7(3.2,-19.2) AG8(4,-19.2) AG9(4.8,-19.2) AG10(5.6,-19.2) AG11(6.4,-19.2) AG12(7.2,-19.2) AG13(8,-19.2) AG14(8.8,-19.2) AG15(9.6,-19.2) AG16(10.4,-19.2) AG17(11.2,-19.2) AG18(12,-19.2) AG19(12.8,-19.2) AG20(13.6,-19.2) AG21(14.4,-19.2) AG22(15.2,-19.2) AG23(16,-19.2) AG24(16.8,-19.2) AG25(17.6,-19.2) AG26(18.4,-19.2) AG27(19.2,-19.2) AG29(20.4,-19.2) AG31(21.2,-19.2) AH6(2.4,-20) AH8(4,-20) AH10(5.6,-20) AH12(7.2,-20) AH14(8.8,-20) AH16(10.4,-20) AH18(12,-20) AH20(13.6,-20) AH22(15.2,-20) AH24(16.8,-20) AH26(18.4,-20) AJ7(3.2,-20.4) AJ9(4.8,-20.4) AJ11(6.4,-20.4) AJ13(8,-20.4) AJ15(9.6,-20.4) AJ17(11.2,-20.4) AJ19(12.8,-20.4) AJ21(14.4,-20.4) AJ23(16,-20.4) AJ25(17.6,-20.4) AJ27(19.2,-20.4) AK6(2.4,-20.8) AK8(4,-20.8) AK10(5.6,-20.8) AK12(7.2,-20.8) AK14(8.8,-20.8) AK16(10.4,-20.8) AK18(12,-20.8) AK20(13.6,-20.8) AK22(15.2,-20.8) AK24(16.8,-20.8) AK26(18.4,-20.8) AL7(3.2,-21.2) AL9(4.8,-21.2) AL11(6.4,-21.2) AL13(8,-21.2) AL15(9.6,-21.2) AL17(11.2,-21.2) AL19(12.8,-21.2) AL21(14.4,-21.2) AL23(16,-21.2) AL25(17.6,-21.2) AL27(19.2,-21.2) AM6(2.4,-21.6) AM8(4,-21.6) AM10(5.6,-21.6) AM12(7.2,-21.6) AM14(8.8,-21.6) AM16(10.4,-21.6) AM18(12,-21.6) AM20(13.6,-21.6) AM22(15.2,-21.6) AM24(16.8,-21.6) AM26(18.4,-21.6) B6(2.4,-0.4) B8(4,-0.4) B10(5.6,-0.4) B12(7.2,-0.4) B14(8.8,-0.4) B16(10.4,-0.4) B18(12,-0.4) B20(13.6,-0.4) B22(15.2,-0.4) B24(16.8,-0.4) B26(18.4,-0.4) C7(3.2,-0.8) C9(4.8,-0.8) C11(6.4,-0.8) C13(8,-0.8) C15(9.6,-0.8) C17(11.2,-0.8) C19(12.8,-0.8) C21(14.4,-0.8) C23(16,-0.8) C25(17.6,-0.8) C27(19.2,-0.8) D6(2.4,-1.2) D8(4,-1.2) D10(5.6,-1.2) D12(7.2,-1.2) D14(8.8,-1.2) D16(10.4,-1.2) D18(12,-1.2) D20(13.6,-1.2) D22(15.2,-1.2) D24(16.8,-1.2) D26(18.4,-1.2) E7(3.2,-1.6) E9(4.8,-1.6) E11(6.4,-1.6) E13(8,-1.6) E15(9.6,-1.6) E17(11.2,-1.6) E19(12.8,-1.6) E21(14.4,-1.6) E23(16,-1.6) E25(17.6,-1.6) E27(19.2,-1.6) F2(0.4,-2.4) F4(1.2,-2.4) F6(2.4,-2.4) F7(3.2,-2.4) F8(4,-2.4) F9(4.8,-2.4) F10(5.6,-2.4) F11(6.4,-2.4) F12(7.2,-2.4) F13(8,-2.4) F14(8.8,-2.4) F15(9.6,-2.4) F16(10.4,-2.4) F17(11.2,-2.4) F18(12,-2.4) F19(12.8,-2.4) F20(13.6,-2.4) F21(14.4,-2.4) F22(15.2,-2.4) F23(16,-2.4) F24(16.8,-2.4) F25(17.6,-2.4) F26(18.4,-2.4) F27(19.2,-2.4) F28(20,-2.4) F30(20.8,-2.4) F32(21.6,-2.4) G1(0,-3.2) G3(0.8,-3.2) G5(1.6,-3.2) G6(2.4,-3.2) G7(3.2,-3.2) G8(4,-3.2) G9(4.8,-3.2) G10(5.6,-3.2) G11(6.6,-3.2) G13(7.8,-3.2) G14(9,-3.2) G16(10.2,-3.2) G17(11.4,-3.2) G19(12.6,-3.2) G20(13.8,-3.2) G22(15,-3.2) G23(16,-3.2) G24(16.8,-3.2) G25(17.6,-3.2) G26(18.4,-3.2) G27(19.2,-3.2) G29(20.4,-3.2) G31(21.2,-3.2) H2(0.4,-4) H4(1.2,-4) H6(2.4,-4) H7(3.2,-4) H8(4,-4) H9(4.8,-4) H10(5.6,-4) H11(6.6,-4) H13(7.8,-4) H14(9,-4) H16(10.2,-4) H17(11.4,-4) H19(12.6,-4) H20(13.8,-4) H22(15,-4) H23(16,-4) H24(16.8,-4) H25(17.6,-4) H26(18.4,-4) H27(19.2,-4) H28(20,-4) H30(20.8,-4) H32(21.6,-4) J1(0,-4.8) J3(0.8,-4.8) J5(1.6,-4.8) J6(2.4,-4.8) J7(3.2,-4.8) J8(4,-4.8) J9(4.8,-4.8) J10(5.6,-4.8) J11(6.6,-4.8) J13(7.8,-4.8) J14(9,-4.8) J16(10.2,-4.8) J17(11.4,-4.8) J19(12.6,-4.8) J20(13.8,-4.8) J22(15,-4.8) J23(16,-4.8) J24(16.8,-4.8) J25(17.6,-4.8) J26(18.4,-4.8) J27(19.2,-4.8) J29(20.4,-4.8) J31(21.2,-4.8) K2(0.4,-5.6) K4(1.2,-5.6) K6(2.4,-5.6) K7(3.2,-5.6) K8(4,-5.6) K9(4.8,-5.6) K10(5.6,-5.6) K11(6.6,-5.6) K13(7.8,-5.6) K14(9,-5.6) K16(10.2,-5.6) K17(11.4,-5.6) K19(12.6,-5.6) K20(13.8,-5.6) K22(15,-5.6) K23(16,-5.6) K24(16.8,-5.6) K25(17.6,-5.6) K26(18.4,-5.6) K27(19.2,-5.6) K28(20,-5.6) K30(20.8,-5.6) K32(21.6,-5.6) L1(0,-6.4) L3(0.8,-6.4) L5(1.6,-6.4) L6(2.4,-6.4) L7(3.2,-6.6) L8(4,-6.6) L9(4.8,-6.6) L10(5.6,-6.6) L23(16,-6.6) L24(16.8,-6.6) L25(17.6,-6.6) L26(18.4,-6.6) L27(19.2,-6.4) L29(20.4,-6.4) L31(21.2,-6.4) M2(0.4,-7.2) M4(1.2,-7.2) M6(2.4,-7.2) M27(19.2,-7.2) M28(20,-7.2) M30(20.8,-7.2) M32(21.6,-7.2) N1(0,-8) N3(0.8,-8) N5(1.6,-8) N6(2.4,-8) N7(3.2,-7.8) N8(4,-7.8) N9(4.8,-7.8) N10(5.6,-7.8) N23(16,-7.8) N24(16.8,-7.8) N25(17.6,-7.8) N26(18.4,-7.8) N27(19.2,-8) N29(20.4,-8) N31(21.2,-8) P2(0.4,-8.8) P4(1.2,-8.8) P6(2.4,-8.8) P7(3.2,-9) P8(4,-9) P9(4.8,-9) P10(5.6,-9) P23(16,-9) P24(16.8,-9) P25(17.6,-9) P26(18.4,-9) P27(19.2,-8.8) P28(20,-8.8) P30(20.8,-8.8) P32(21.6,-8.8) R1(0,-9.6) R3(0.8,-9.6) R5(1.6,-9.6) R6(2.4,-9.6) R27(19.2,-9.6) R29(20.4,-9.6) R31(21.2,-9.6) T2(0.4,-10.4) T4(1.2,-10.4) T6(2.4,-10.4) T7(3.2,-10.2) T8(4,-10.2) T9(4.8,-10.2) T10(5.6,-10.2) T23(16,-10.2) T24(16.8,-10.2) T25(17.6,-10.2) T26(18.4,-10.2) T27(19.2,-10.4) T28(20,-10.4) T30(20.8,-10.4) T32(21.6,-10.4) U1(0,-11.2) U3(0.8,-11.2) U5(1.6,-11.2) U6(2.4,-11.2) U7(3.2,-11.4) U8(4,-11.4) U9(4.8,-11.4) U10(5.6,-11.4) U23(16,-11.4) U24(16.8,-11.4) U25(17.6,-11.4) U26(18.4,-11.4) U27(19.2,-11.2) U29(20.4,-11.2) U31(21.2,-11.2) V2(0.4,-12) V4(1.2,-12) V6(2.4,-12) V27(19.2,-12) V28(20,-12) V30(20.8,-12) V32(21.6,-12) W1(0,-12.8) W3(0.8,-12.8) W5(1.6,-12.8) W6(2.4,-12.8) W7(3.2,-12.6) W8(4,-12.6) W9(4.8,-12.6) W10(5.6,-12.6) W23(16,-12.6) W24(16.8,-12.6) W25(17.6,-12.6) W26(18.4,-12.6) W27(19.2,-12.8) W29(20.4,-12.8) W31(21.2,-12.8) Y2(0.4,-13.6) Y4(1.2,-13.6) Y6(2.4,-13.6) Y7(3.2,-13.8) Y8(4,-13.8) Y9(4.8,-13.8) Y10(5.6,-13.8) Y23(16,-13.8) Y24(16.8,-13.8) Y25(17.6,-13.8) Y26(18.4,-13.8) Y27(19.2,-13.6) Y28(20,-13.6) Y30(20.8,-13.6) Y32(21.6,-13.6)
  round 0.508 smd: AA11(6.4,-14.2) AA12(7.4,-14.2) AA13(8.4,-14.2) AA15(9.4,-14.2) AA16(10.4,-14.2) AA17(11.2,-14.2) AA18(12.2,-14.2) AA20(13.2,-14.2) AA21(14.2,-14.2) AA22(15.2,-14.2) AB11(6.4,-15.2) AB12(7.4,-15.2) AB13(8.4,-15.2) AB15(9.4,-15.2) AB16(10.4,-15.2) AB17(11.2,-15.2) AB18(12.2,-15.2) AB20(13.2,-15.2) AB21(14.2,-15.2) AB22(15.2,-15.2) L11(6.4,-6.4) L12(7.4,-6.4) L13(8.4,-6.4) L15(9.4,-6.4) L16(10.4,-6.4) L17(11.2,-6.4) L18(12.2,-6.4) L20(13.2,-6.4) L21(14.2,-6.4) L22(15.2,-6.4) M11(6.4,-7.4) M12(7.4,-7.4) M13(8.4,-7.4) M15(9.4,-7.4) M16(10.4,-7.4) M17(11.2,-7.4) M18(12.2,-7.4) M20(13.2,-7.4) M21(14.2,-7.4) M22(15.2,-7.4) N11(6.4,-8.4) N12(7.4,-8.4) N13(8.4,-8.4) N15(9.4,-8.4) N16(10.4,-8.4) N17(11.2,-8.4) N18(12.2,-8.4) N20(13.2,-8.4) N21(14.2,-8.4) N22(15.2,-8.4) R11(6.4,-9.4) R12(7.4,-9.4) R13(8.4,-9.4) R15(9.4,-9.4) R16(10.4,-9.4) R17(11.2,-9.4) R18(12.2,-9.4) R20(13.2,-9.4) R21(14.2,-9.4) R22(15.2,-9.4) T11(6.4,-10.4) T12(7.4,-10.4) T13(8.4,-10.4) T15(9.4,-10.4) T16(10.4,-10.4) T17(11.2,-10.4) T18(12.2,-10.4) T20(13.2,-10.4) T21(14.2,-10.4) T22(15.2,-10.4) U11(6.4,-11.2) U12(7.4,-11.2) U13(8.4,-11.2) U15(9.4,-11.2) U16(10.4,-11.2) U17(11.2,-11.2) U18(12.2,-11.2) U20(13.2,-11.2) U21(14.2,-11.2) U22(15.2,-11.2) V11(6.4,-12.2) V12(7.4,-12.2) V13(8.4,-12.2) V15(9.4,-12.2) V16(10.4,-12.2) V17(11.2,-12.2) V18(12.2,-12.2) V20(13.2,-12.2) V21(14.2,-12.2) V22(15.2,-12.2) Y11(6.4,-13.2) Y12(7.4,-13.2) Y13(8.4,-13.2) Y15(9.4,-13.2) Y16(10.4,-13.2) Y17(11.2,-13.2) Y18(12.2,-13.2) Y20(13.2,-13.2) Y21(14.2,-13.2) Y22(15.2,-13.2)
ACES_50463-0104A-P01_10P-T
  oval 0.203x1.194 smd: 1(0,0) 2(-0.4,0) 3(-0.8,0) 4(-1.2,0) 5(-1.6,0) 6(-2,0) 7(-2.4,0) 8(-2.8,0) 9(-3.2,0) 10(-3.6,0)
  rect 1.397x2.007 smd: 11(2.5,1.37) 12(-6.1,1.37)
